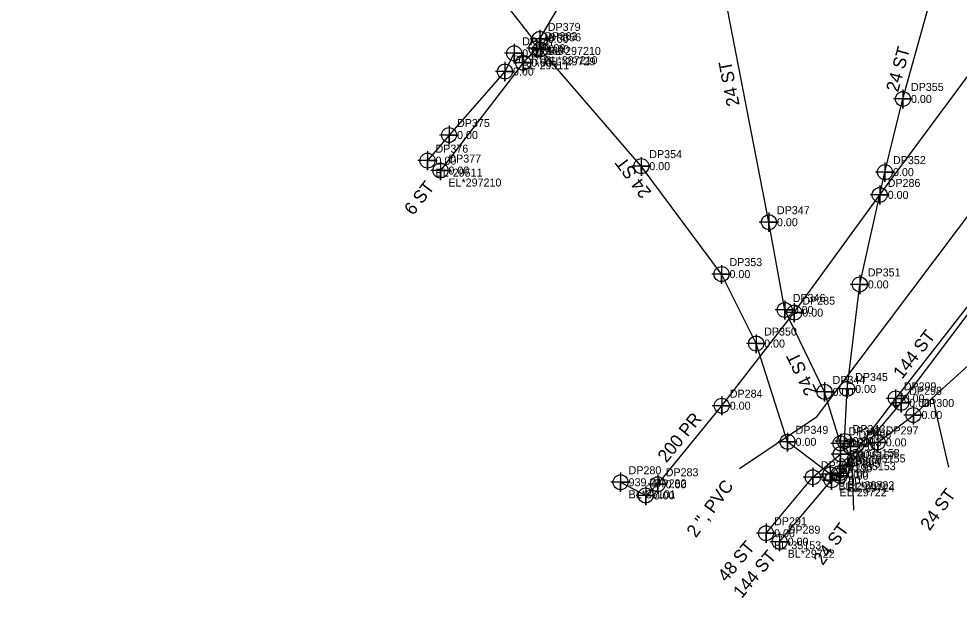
# Model space of a CAD drawing. Extents: x 1182504 to 1186036, y 573002 to 575111.
# Drawn here: x 1183573.3 to 1183867, y 573002.3 to 573183.3 of the extents above; entities that cross this region are included whole.
import ezdxf

# ---------------------------------------------------------------- set-up
doc = ezdxf.new("R2010")
doc.units = 0
for name, color, linetype in [('Exist Utilities Power UG Cable SUE LOS B', 7, 'Continuous'), ('Exist Utilities Power UG Cable SUE LOS B Cogo Comment', 7, 'Continuous'), ('Exist Utilities Power UG Cable SUE LOS B Cogo Elevation', 7, 'Continuous'), ('Exist Utilities Power UG Cable SUE LOS B Cogo Number', 7, 'Continuous'), ('Exist Utilities Power UG Cable SUE LOS B Cogo Point CELL', 7, 'Continuous'), ('Exist Utilities Telephone UG Cable SUE LOS C', 7, 'Continuous'), ('Exist Utilities Telephone UG Cable SUE LOS C Cogo Comment', 7, 'Continuous'), ('Exist Utilities Telephone UG Cable SUE LOS C Cogo Elevation', 7, 'Continuous'), ('Exist Utilities Telephone UG Cable SUE LOS C Cogo Number', 7, 'Continuous'), ('Exist Utilities Telephone UG Cable SUE LOS C Cogo Point CELL', 7, 'Continuous'), ('Exist Utilities Telephone UG Cable SUE LOS C Text', 7, 'Continuous'), ('Exist Utilities Telephone UG Conduit SUE LOS B', 7, 'Continuous'), ('Exist Utilities Telephone UG Conduit SUE LOS B Cogo Comment', 7, 'Continuous'), ('Exist Utilities Telephone UG Conduit SUE LOS B Cogo Elevation', 7, 'Continuous'), ('Exist Utilities Telephone UG Conduit SUE LOS B Cogo Number', 7, 'Continuous'), ('Exist Utilities Telephone UG Conduit SUE LOS B Cogo Point CELL', 7, 'Continuous'), ('Exist Utilities Telephone UG Conduit SUE LOS B Leader', 7, 'Continuous'), ('Exist Utilities Telephone UG Conduit SUE LOS B Text', 7, 'Continuous'), ('Exist Utilities Telephone UG FO SUE LOS C', 7, 'Continuous'), ('Exist Utilities Telephone UG FO SUE LOS C Cogo Comment', 7, 'Continuous'), ('Exist Utilities Telephone UG FO SUE LOS C Cogo Elevation', 7, 'Continuous'), ('Exist Utilities Telephone UG FO SUE LOS C Cogo Number', 7, 'Continuous'), ('Exist Utilities Telephone UG FO SUE LOS C Cogo Point CELL', 7, 'Continuous'), ('Exist Utilities Telephone UG FO SUE LOS C Leader', 7, 'Continuous'), ('Exist Utilities Telephone UG FO SUE LOS C Text', 7, 'Continuous'), ('Exist Utilities Water UG Line SUE LOS C', 7, 'Continuous'), ('Exist Utilities Water UG Line SUE LOS C Leader', 7, 'Continuous'), ('Exist Utilities Water UG Line SUE LOS C Text', 7, 'Continuous')]:
    doc.layers.add(name, color=color, linetype=linetype)

msp = doc.modelspace()

# ---------------------------------------------------------------- linework, layer by layer
at = {"layer": 'Exist Utilities Power UG Cable SUE LOS B'}
msp.add_lwpolyline([(1183728.02, 573172.53), (1183725.14, 573166.84), (1183707.68, 573147.01), (1183700.95, 573139)], dxfattribs=at)
at = {"layer": 'Exist Utilities Power UG Cable SUE LOS B Cogo Point CELL'}
for points in [[(1183728.02, 573175.53), (1183728.02, 573169.53), (1183728.02, 573172.53), (1183731.02, 573172.53), (1183725.02, 573172.53)], [(1183725.14, 573169.84), (1183725.14, 573163.84), (1183725.14, 573166.84), (1183728.14, 573166.84), (1183722.14, 573166.84)], [(1183707.68, 573150.01), (1183707.68, 573144.01), (1183707.68, 573147.01), (1183710.68, 573147.01), (1183704.68, 573147.01)], [(1183700.95, 573142), (1183700.95, 573136), (1183700.95, 573139), (1183703.95, 573139), (1183697.95, 573139)]]:
    msp.add_lwpolyline(points, dxfattribs=at)
for centre in [(1183728.02, 573172.53), (1183725.14, 573166.84), (1183707.68, 573147.01), (1183700.95, 573139)]:
    msp.add_circle(centre, 2.34, dxfattribs=at)
at = {"layer": 'Exist Utilities Telephone UG Cable SUE LOS C'}
msp.add_lwpolyline([(1183761.25, 573038.53), (1183769.09, 573034.41), (1183772.83, 573037.9), (1183792.84, 573062.44), (1183815.5, 573091.52), (1183842.15, 573128.3), (1183871.65, 573168.11), (1183894.45, 573200.64), (1183915.52, 573231.01), (1183941.95, 573268.28), (1183966.78, 573306.07), (1183979.43, 573323.54), (1183993.99, 573342.83), (1184020.65, 573379.96), (1184047.47, 573417.15), (1184074.68, 573455.3), (1184101.33, 573490.9), (1184089.43, 573505.28)], dxfattribs=at)
at = {"layer": 'Exist Utilities Telephone UG Cable SUE LOS C Cogo Point CELL'}
for points in [[(1183842.15, 573131.3), (1183842.15, 573125.3), (1183842.15, 573128.3), (1183845.15, 573128.3), (1183839.15, 573128.3)], [(1183815.5, 573094.52), (1183815.5, 573088.52), (1183815.5, 573091.52), (1183818.5, 573091.52), (1183812.5, 573091.52)], [(1183792.84, 573065.44), (1183792.84, 573059.44), (1183792.84, 573062.44), (1183795.84, 573062.44), (1183789.84, 573062.44)], [(1183761.25, 573041.53), (1183761.25, 573035.53), (1183761.25, 573038.53), (1183764.25, 573038.53), (1183758.25, 573038.53)], [(1183772.83, 573040.9), (1183772.83, 573034.9), (1183772.83, 573037.9), (1183775.83, 573037.9), (1183769.83, 573037.9)], [(1183769.09, 573037.41), (1183769.09, 573031.41), (1183769.09, 573034.41), (1183772.09, 573034.41), (1183766.09, 573034.41)]]:
    msp.add_lwpolyline(points, dxfattribs=at)
for centre in [(1183842.15, 573128.3), (1183815.5, 573091.52), (1183792.84, 573062.44), (1183761.25, 573038.53), (1183772.83, 573037.9), (1183769.09, 573034.41)]:
    msp.add_circle(centre, 2.34, dxfattribs=at)
at = {"layer": 'Exist Utilities Telephone UG Conduit SUE LOS B'}
msp.add_line((1183810.91, 573019.96), (1183827.14, 573039.14), dxfattribs=at)
for points in [[(1183829.51, 573041.35), (1183847.15, 573064.74), (1183871.66, 573096.02), (1183886.35, 573114.73), (1183900.1, 573133.86), (1183912.38, 573150.76), (1183937.09, 573185.03), (1183964.91, 573224.98), (1183990.4, 573262.6), (1184013.24, 573293.53), (1184021.26, 573304.97)], [(1183829.66, 573040.59), (1183848.87, 573063.35), (1183872.59, 573094.91), (1183886.95, 573113.99), (1183900.66, 573133.04), (1183912.9, 573150.17), (1183937.83, 573184.45), (1183965.61, 573224.4), (1183991.1, 573261.97), (1184013.84, 573292.77), (1184021.83, 573304.52)], [(1183734.02, 573176.9), (1183691.83, 573230.97), (1183669.62, 573254.07), (1183642.4, 573259.08), (1183573.33, 573253.19)], [(1183826.74, 573041.02), (1183813.39, 573051.16), (1183803.57, 573081.86), (1183792.75, 573103.56), (1183767.71, 573137.29), (1183736.2, 573173.77)]]:
    msp.add_lwpolyline(points, dxfattribs=at)
at = {"layer": 'Exist Utilities Telephone UG Conduit SUE LOS B Cogo Point CELL'}
for points in [[(1183736, 573179.85), (1183736.03, 573174.04), (1183736.02, 573177.04), (1183739.03, 573177.04), (1183733.03, 573177.04)], [(1183734.97, 573176.94), (1183735, 573171.13), (1183734.98, 573174.13), (1183738, 573174.13), (1183732, 573174.13)], [(1183736.18, 573176.59), (1183736.21, 573170.77), (1183736.2, 573173.77), (1183739.21, 573173.77), (1183733.21, 573173.77)], [(1183730.79, 573172.4), (1183730.82, 573166.59), (1183730.81, 573169.59), (1183733.82, 573169.59), (1183727.82, 573169.59)], [(1183767.69, 573140.1), (1183767.73, 573134.29), (1183767.71, 573137.29), (1183770.73, 573137.29), (1183764.73, 573137.29)], [(1183704.97, 573138.74), (1183705, 573132.92), (1183704.98, 573135.92), (1183708, 573135.92), (1183702, 573135.92)], [(1183792.74, 573106.37), (1183792.77, 573100.56), (1183792.75, 573103.56), (1183795.77, 573103.56), (1183789.77, 573103.56)], [(1183803.56, 573084.68), (1183803.59, 573078.86), (1183803.57, 573081.86), (1183806.59, 573081.86), (1183800.59, 573081.86)], [(1183847.14, 573067.56), (1183847.17, 573061.74), (1183847.15, 573064.74), (1183850.17, 573064.74), (1183844.17, 573064.74)], [(1183848.85, 573066.16), (1183848.88, 573060.35), (1183848.87, 573063.35), (1183851.88, 573063.35), (1183845.88, 573063.35)], [(1183813.37, 573053.98), (1183813.41, 573048.16), (1183813.39, 573051.16), (1183816.41, 573051.16), (1183810.41, 573051.16)], [(1183826.72, 573043.84), (1183826.76, 573038.02), (1183826.74, 573041.02), (1183829.76, 573041.02), (1183823.76, 573041.02)], [(1183829.49, 573044.17), (1183829.52, 573038.35), (1183829.51, 573041.35), (1183832.52, 573041.35), (1183826.52, 573041.35)], [(1183829.64, 573043.4), (1183829.67, 573037.59), (1183829.66, 573040.59), (1183832.67, 573040.59), (1183826.67, 573040.59)], [(1183827.12, 573041.95), (1183827.16, 573036.14), (1183827.14, 573039.14), (1183830.16, 573039.14), (1183824.16, 573039.14)], [(1183810.89, 573022.77), (1183810.92, 573016.96), (1183810.91, 573019.96), (1183813.92, 573019.96), (1183807.92, 573019.96)]]:
    msp.add_lwpolyline(points, dxfattribs=at)
for centre in [(1183736.03, 573177.04), (1183735, 573174.13), (1183736.21, 573173.77), (1183730.82, 573169.59), (1183767.73, 573137.29), (1183705, 573135.92), (1183792.77, 573103.56), (1183803.59, 573081.86), (1183847.17, 573064.74), (1183848.88, 573063.35), (1183813.41, 573051.16), (1183826.76, 573041.02), (1183829.52, 573041.35), (1183829.67, 573040.59), (1183827.16, 573039.14), (1183810.92, 573019.96)]:
    msp.add_circle(centre, 2.34, dxfattribs=at)
at = {"layer": 'Exist Utilities Telephone UG Conduit SUE LOS B Leader'}
msp.add_line((1183833.43, 573045.05), (1183834.01, 573029.78), dxfattribs=at)
at = {"layer": 'Exist Utilities Telephone UG FO SUE LOS C'}
for points in [[(1183831.2, 573051.4), (1183831.99, 573067.67), (1183835.94, 573100.34), (1183843.81, 573135.41), (1183849.42, 573158.28), (1183872.21, 573240.17), (1183881.95, 573271.33), (1183882.59, 573295.88), (1183881.95, 573329.75), (1183881.17, 573370.19), (1183880.74, 573416.08), (1183881.11, 573461.73), (1183880.38, 573505.49), (1183880.23, 573552), (1183881.56, 573597.96), (1183880.77, 573642.04), (1183880.14, 573689.54)], [(1183833.03, 573049.72), (1183841.55, 573050.99), (1183852.69, 573059.54), (1183874.36, 573079.14), (1183890.55, 573095.13), (1183891.68, 573098.9), (1183894.04, 573137.68), (1183901.8, 573155.08), (1183929.9, 573193.57), (1183954.83, 573228.84), (1183982.65, 573265.33), (1183993.74, 573274.22), (1184002.17, 573271.91), (1184013.15, 573265.94), (1184039.54, 573239.83), (1184068.08, 573211.39), (1184123.17, 573153.72), (1184151.22, 573123.17)], [(1183736.02, 573177.04), (1183747.89, 573197.26), (1183763.45, 573220.41)], [(1183829.91, 573050.69), (1183824.94, 573066.76), (1183812.49, 573092.36), (1183807.57, 573119.77), (1183793.41, 573192.85)], [(1183734.98, 573174.13), (1183730.81, 573169.59), (1183704.98, 573135.92)], [(1183806.68, 573022.6), (1183821.27, 573040.09), (1183829.97, 573047.3)]]:
    msp.add_lwpolyline(points, dxfattribs=at)
at = {"layer": 'Exist Utilities Telephone UG FO SUE LOS C Cogo Point CELL'}
for points in [[(1183849.42, 573161.28), (1183849.42, 573155.28), (1183849.42, 573158.28), (1183852.42, 573158.28), (1183846.42, 573158.28)], [(1183843.81, 573138.41), (1183843.81, 573132.41), (1183843.81, 573135.41), (1183846.81, 573135.41), (1183840.81, 573135.41)], [(1183807.57, 573122.77), (1183807.57, 573116.77), (1183807.57, 573119.77), (1183810.57, 573119.77), (1183804.57, 573119.77)], [(1183835.94, 573103.34), (1183835.94, 573097.34), (1183835.94, 573100.34), (1183838.94, 573100.34), (1183832.94, 573100.34)], [(1183812.49, 573095.36), (1183812.49, 573089.36), (1183812.49, 573092.36), (1183815.49, 573092.36), (1183809.49, 573092.36)], [(1183824.94, 573069.76), (1183824.94, 573063.76), (1183824.94, 573066.76), (1183827.94, 573066.76), (1183821.94, 573066.76)], [(1183831.99, 573070.67), (1183831.99, 573064.67), (1183831.99, 573067.67), (1183834.99, 573067.67), (1183828.99, 573067.67)], [(1183852.69, 573062.54), (1183852.69, 573056.54), (1183852.69, 573059.54), (1183855.69, 573059.54), (1183849.69, 573059.54)], [(1183831.2, 573054.4), (1183831.2, 573048.4), (1183831.2, 573051.4), (1183834.2, 573051.4), (1183828.2, 573051.4)], [(1183829.91, 573053.69), (1183829.91, 573047.69), (1183829.91, 573050.69), (1183832.91, 573050.69), (1183826.91, 573050.69)], [(1183833.03, 573052.72), (1183833.03, 573046.72), (1183833.03, 573049.72), (1183836.03, 573049.72), (1183830.03, 573049.72)], [(1183841.55, 573053.99), (1183841.55, 573047.99), (1183841.55, 573050.99), (1183844.55, 573050.99), (1183838.55, 573050.99)], [(1183829.97, 573050.3), (1183829.97, 573044.3), (1183829.97, 573047.3), (1183832.97, 573047.3), (1183826.97, 573047.3)], [(1183821.27, 573043.09), (1183821.27, 573037.09), (1183821.27, 573040.09), (1183824.27, 573040.09), (1183818.27, 573040.09)], [(1183806.68, 573025.6), (1183806.68, 573019.6), (1183806.68, 573022.6), (1183809.68, 573022.6), (1183803.68, 573022.6)]]:
    msp.add_lwpolyline(points, dxfattribs=at)
for centre in [(1183849.42, 573158.28), (1183843.81, 573135.41), (1183807.57, 573119.77), (1183835.94, 573100.34), (1183812.49, 573092.36), (1183824.94, 573066.76), (1183831.99, 573067.67), (1183852.69, 573059.54), (1183829.91, 573050.69), (1183831.2, 573051.4), (1183833.03, 573049.72), (1183841.55, 573050.99), (1183829.97, 573047.3), (1183821.27, 573040.09), (1183806.68, 573022.6)]:
    msp.add_circle(centre, 2.34, dxfattribs=at)
at = {"layer": 'Exist Utilities Telephone UG FO SUE LOS C Leader'}
msp.add_line((1183858.64, 573064.92), (1183863.68, 573043.23), dxfattribs=at)
at = {"layer": 'Exist Utilities Water UG Line SUE LOS C'}
msp.add_line((1183822.46, 573058.84), (1183995.12, 573288.87), dxfattribs=at)
at = {"layer": 'Exist Utilities Water UG Line SUE LOS C Leader'}
msp.add_line((1183822.46, 573058.84), (1183798.35, 573042.72), dxfattribs=at)

# ---------------------------------------------------------------- texts
at = {"layer": 'Exist Utilities Power UG Cable SUE LOS B Cogo Comment'}
for s, p in [('BL*29511', (1183730.52, 573167.53)), ('EL*29511', (1183703.45, 573134))]:
    msp.add_text(s, height=2.5, dxfattribs=at).set_placement(p)
at = {"layer": 'Exist Utilities Power UG Cable SUE LOS B Cogo Elevation'}
for p in [(1183730.52, 573171.28), (1183727.64, 573165.59), (1183710.18, 573145.76), (1183703.45, 573137.75)]:
    msp.add_text('0.00', height=2.5, dxfattribs=at).set_placement(p)
at = {"layer": 'Exist Utilities Power UG Cable SUE LOS B Cogo Number'}
for s, p in [('DP367', (1183730.52, 573175.03)), ('DP370', (1183727.64, 573169.34)), ('DP375', (1183710.18, 573149.51)), ('DP376', (1183703.45, 573141.5))]:
    msp.add_text(s, height=2.5, dxfattribs=at).set_placement(p)
at = {"layer": 'Exist Utilities Telephone UG Cable SUE LOS C Cogo Comment'}
msp.add_text('BL*35101', height=2.5, dxfattribs=at).set_placement((1183763.75, 573033.53))
at = {"layer": 'Exist Utilities Telephone UG Cable SUE LOS C Cogo Elevation'}
for s, p in [('0.00', (1183844.65, 573127.05)), ('0.00', (1183818, 573090.27)), ('0.00', (1183795.34, 573061.19)), ('939.24', (1183763.75, 573037.28)), ('0.00', (1183775.33, 573036.65)), ('0.00', (1183771.59, 573033.16))]:
    msp.add_text(s, height=2.5, dxfattribs=at).set_placement(p)
at = {"layer": 'Exist Utilities Telephone UG Cable SUE LOS C Cogo Number'}
for s, p in [('DP286', (1183844.65, 573130.8)), ('DP285', (1183818, 573094.02)), ('DP284', (1183795.34, 573064.94)), ('DP280', (1183763.75, 573041.03)), ('DP283', (1183775.33, 573040.4)), ('DP282', (1183771.59, 573036.91))]:
    msp.add_text(s, height=2.5, dxfattribs=at).set_placement(p)
at = {"layer": 'Exist Utilities Telephone UG Cable SUE LOS C Text'}
msp.add_text('200 PR', height=4, rotation=50.8023, dxfattribs=at).set_placement((1183775.56, 573044.41))
at = {"layer": 'Exist Utilities Telephone UG Conduit SUE LOS B Cogo Comment'}
for s, p in [('BL*297210', (1183738.52, 573172.04)), ('BL*297210', (1183737.48, 573169.13)), ('EL*29729', (1183738.7, 573168.77)), ('EL*297210', (1183707.48, 573130.92)), ('BL*29729', (1183829.24, 573036.02)), ('BL*29722', (1183832.01, 573036.35)), ('BL*29724', (1183832.16, 573035.59)), ('EL*29722', (1183829.64, 573034.14)), ('BL*29722', (1183813.41, 573014.96))]:
    msp.add_text(s, height=2.5, dxfattribs=at).set_placement(p)
at = {"layer": 'Exist Utilities Telephone UG Conduit SUE LOS B Cogo Elevation'}
for p in [(1183738.52, 573175.79), (1183737.48, 573172.88), (1183738.7, 573172.52), (1183733.31, 573168.34), (1183707.48, 573134.67), (1183770.21, 573136.04), (1183795.25, 573102.31), (1183806.07, 573080.61), (1183849.65, 573063.49), (1183851.37, 573062.1), (1183815.89, 573049.91), (1183832.01, 573040.1), (1183829.24, 573039.77), (1183829.64, 573037.89), (1183832.16, 573039.34), (1183813.41, 573018.71)]:
    msp.add_text('0.00', height=2.5, dxfattribs=at).set_placement(p)
at = {"layer": 'Exist Utilities Telephone UG Conduit SUE LOS B Cogo Number'}
for s, p in [('DP379', (1183738.52, 573179.54)), ('DP363', (1183737.48, 573176.63)), ('DP356', (1183738.7, 573176.27)), ('DP366', (1183733.31, 573172.09)), ('DP377', (1183707.48, 573138.42)), ('DP354', (1183770.21, 573139.79)), ('DP353', (1183795.25, 573106.06)), ('DP350', (1183806.07, 573084.36)), ('DP299', (1183849.65, 573067.24)), ('DP298', (1183851.37, 573065.85)), ('DP349', (1183815.89, 573053.66)), ('DP348', (1183829.24, 573043.52)), ('DP294', (1183832.01, 573043.85)), ('DP295', (1183832.16, 573043.09)), ('DP290', (1183829.64, 573041.64)), ('DP289', (1183813.41, 573022.46))]:
    msp.add_text(s, height=2.5, dxfattribs=at).set_placement(p)
at = {"layer": 'Exist Utilities Telephone UG Conduit SUE LOS B Text'}
for s, rotation, p in [('24 ST', 126.5897, (1183771.03, 573129.13)), ('144 ST', 51.9107, (1183849.14, 573070.53)), ('24 ST', 53.9157, (1183824.37, 573012.35)), ('144 ST', 49.7549, (1183799.04, 573002))]:
    msp.add_text(s, height=4, rotation=rotation, dxfattribs=at).set_placement(p)
at = {"layer": 'Exist Utilities Telephone UG FO SUE LOS C Cogo Comment'}
for s, p in [('BL*35158', (1183833.7, 573046.4)), ('BL*35157', (1183832.41, 573045.69)), ('BL*35155', (1183835.53, 573044.72)), ('EL*35153', (1183832.47, 573042.3)), ('BL*35153', (1183809.18, 573017.6))]:
    msp.add_text(s, height=2.5, dxfattribs=at).set_placement(p)
at = {"layer": 'Exist Utilities Telephone UG FO SUE LOS C Cogo Elevation'}
for p in [(1183851.92, 573157.03), (1183846.31, 573134.16), (1183810.07, 573118.52), (1183838.44, 573099.09), (1183814.99, 573091.11), (1183827.44, 573065.51), (1183834.49, 573066.42), (1183855.19, 573058.29), (1183832.41, 573049.44), (1183833.7, 573050.15), (1183844.05, 573049.74), (1183832.47, 573046.05), (1183835.53, 573048.47), (1183823.77, 573038.84), (1183809.18, 573021.35)]:
    msp.add_text('0.00', height=2.5, dxfattribs=at).set_placement(p)
at = {"layer": 'Exist Utilities Telephone UG FO SUE LOS C Cogo Number'}
for s, p in [('DP355', (1183851.92, 573160.78)), ('DP352', (1183846.31, 573137.91)), ('DP347', (1183810.07, 573122.27)), ('DP351', (1183838.44, 573102.84)), ('DP346', (1183814.99, 573094.86)), ('DP345', (1183834.49, 573070.17)), ('DP344', (1183827.44, 573069.26)), ('DP300', (1183855.19, 573062.04)), ('DP342', (1183832.41, 573053.19)), ('DP343', (1183833.7, 573053.9)), ('DP296', (1183835.53, 573052.22)), ('DP297', (1183844.05, 573053.49)), ('DP293', (1183832.47, 573049.8)), ('DP292', (1183823.77, 573042.59)), ('DP291', (1183809.18, 573025.1))]:
    msp.add_text(s, height=2.5, dxfattribs=at).set_placement(p)
at = {"layer": 'Exist Utilities Telephone UG FO SUE LOS C Text'}
for s, rotation, p in [('24 ST', 74.4485, (1183847.88, 573160.19)), ('24 ST', 100.9686, (1183798.44, 573156.4)), ('6 ST', 52.508, (1183696.48, 573121.67)), ('24 ST', 115.9228, (1183822.69, 573066.8)), ('24 ST', 53.9157, (1183857.73, 573023.13)), ('48 ST', 50.1574, (1183794.28, 573007.13))]:
    msp.add_text(s, height=4, rotation=rotation, dxfattribs=at).set_placement(p)
at = {"layer": 'Exist Utilities Water UG Line SUE LOS C Text'}
msp.add_text('2 ", PVC', height=4, rotation=53.9157, dxfattribs=at).set_placement((1183784.75, 573020.98))

doc.saveas('drawing.dxf')
